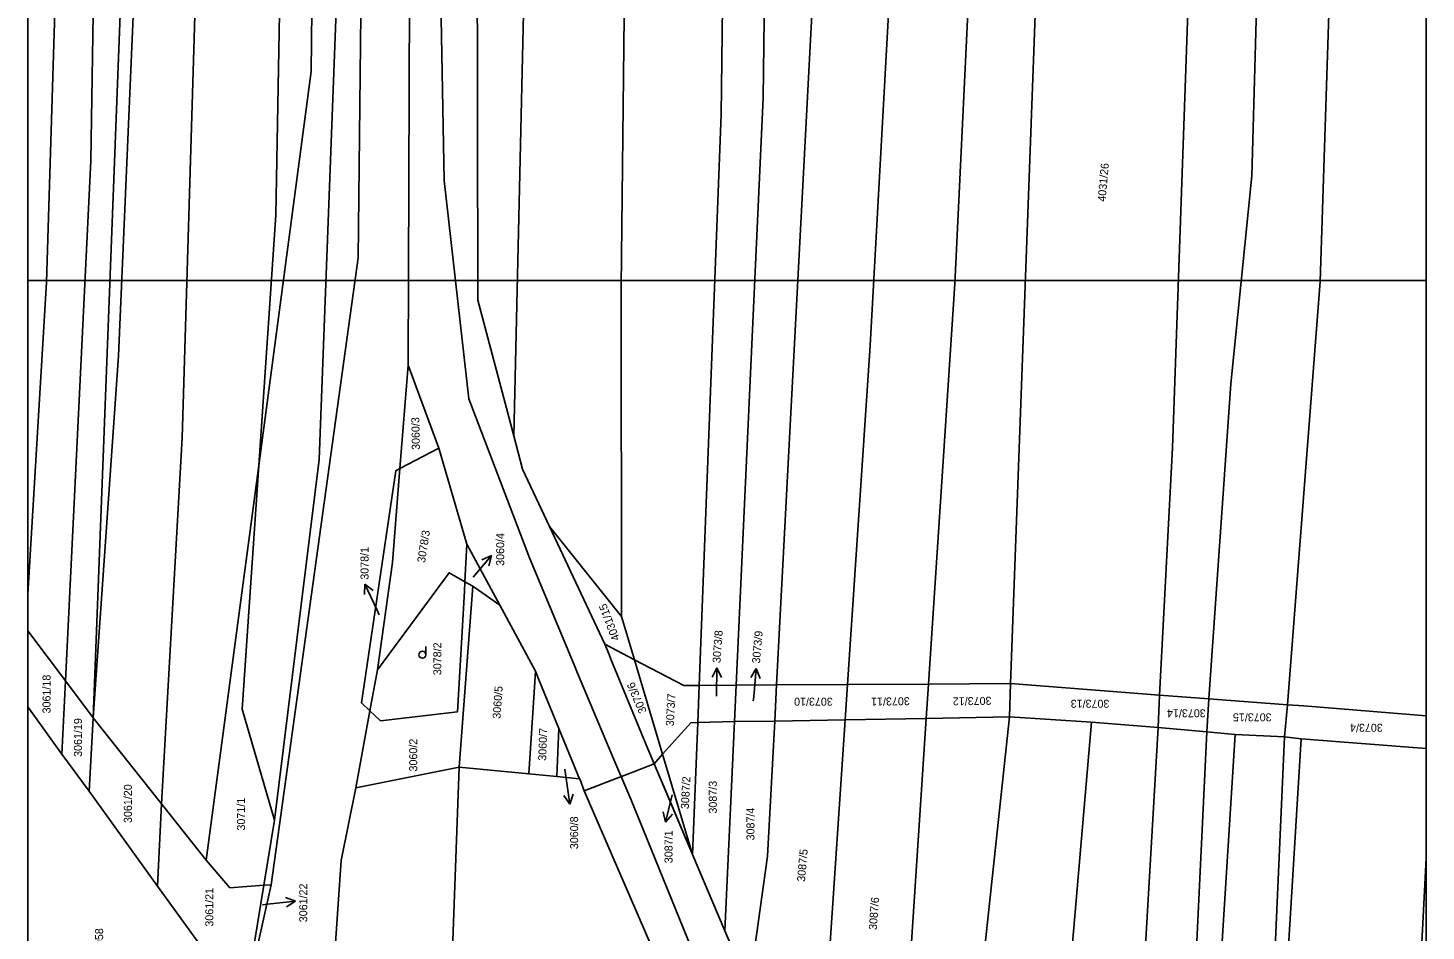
# Model space of a CAD drawing. Extents: x -534410 to -534262, y -1190162 to -1189584.
# Drawn here: x -534410.1 to -534261.6, y -1189968.6 to -1189872.7 of the extents above; entities that cross this region are included whole.
import ezdxf

# ---------------------------------------------------------------- set-up
doc = ezdxf.new("R2010")
doc.units = 0
for name, color, linetype in [('_KN_Povodí_Moravy', 7, 'Continuous'), ('_N_osa', 7, 'Continuous'), ('_rámeček', 7, 'Continuous'), ('_rámeček_mřížka', 7, 'Continuous'), ('Hranice parcel', 7, 'Continuous'), ('Parcelní čísla', 7, 'Continuous'), ('Pop  PČ popisy', 7, 'Continuous'), ('Značky kultur', 7, 'Continuous')]:
    doc.layers.add(name, color=color, linetype=linetype)

msp = doc.modelspace()

# ---------------------------------------------------------------- linework, layer by layer
at = {"layer": '_KN_Povodí_Moravy'}
for p, q in [((-534369.38, -1189820.8), (-534369.75, -1189908.47)), ((-534358.53, -1189915.98), (-534362.34, -1189901.56)), ((-534369.75, -1189908.47), (-534366.49, -1189917.27)), ((-534366.49, -1189917.27), (-534363.5, -1189927.49)), ((-534348.85, -1189938.1), (-534354.73, -1189925.6)), ((-534360.01, -1189933.96), (-534356.23, -1189940.98)), ((-534356.23, -1189940.98), (-534355.84, -1189941.94)), ((-534355.84, -1189941.94), (-534353.75, -1189947.04)), ((-534353.75, -1189947.04), (-534351.79, -1189951.81)), ((-534346.53, -1189951.94), (-534343.61, -1189950.82)), ((-534351.52, -1189952.39), (-534351.04, -1189953.66)), ((-534351.04, -1189953.66), (-534347.64, -1189952.36)), ((-534347.64, -1189952.36), (-534346.53, -1189951.94)), ((-534351.04, -1189953.66), (-534341.9, -1189974.75)), ((-534336.09, -1189968.55), (-534339.54, -1189960.43)), ((-534333.52, -1189974.6), (-534336.09, -1189968.55))]:
    msp.add_line(p, q, dxfattribs=at)
for points in [[(-534362.34, -1189901.56), (-534362.6, -1189764.35), (-534359.48, -1189697.97)], [(-534354.73, -1189925.6), (-534357.59, -1189919.52), (-534358.53, -1189915.98)], [(-534363.5, -1189927.49), (-534362.09, -1189930.1), (-534360.01, -1189933.96)], [(-534343.61, -1189950.82), (-534344.09, -1189949.7), (-534344.29, -1189949.21), (-534348.2, -1189939.68), (-534348.39, -1189939.21), (-534348.85, -1189938.1)], [(-534343.61, -1189950.82), (-534346.53, -1189951.94), (-534347.64, -1189952.36), (-534351.04, -1189953.66)], [(-534339.54, -1189960.43), (-534341.89, -1189954.88), (-534343.61, -1189950.82)], [(-534351.79, -1189951.81), (-534351.6, -1189952.27), (-534351.52, -1189952.39)]]:
    msp.add_lwpolyline(points, dxfattribs=at)
at = {"layer": '_N_osa'}
for points in [[(-534351.95, -1189940.72), (-534356.84, -1189928.92), (-534363.29, -1189912.04), (-534365.92, -1189888.84), (-534366.71, -1189846.73), (-534366.46, -1189820.49), (-534366.39, -1189779.5), (-534366.3, -1189748.87), (-534365.06, -1189684.89), (-534363.19, -1189653.56), (-534361.33, -1189627.82)], [(-534347.89, -1189950.33), (-534351.93, -1189940.77), (-534351.95, -1189940.72)], [(-534327.36, -1190134.6), (-534324.33, -1190120.41), (-534323.46, -1190078.16), (-534322.63, -1190051.74), (-534322.66, -1190021.45), (-534325.42, -1190005.39), (-534346.1, -1189954.57), (-534347.89, -1189950.33)]]:
    msp.add_lwpolyline(points, dxfattribs=at)
at = {"layer": '_rámeček'}
msp.add_line((-534410.13, -1189584.47), (-534410.13, -1190161.97), dxfattribs=at)
msp.add_lwpolyline([(-534410.13, -1190161.97), (-534261.63, -1190161.97), (-534261.63, -1189584.47)], dxfattribs=at)
for points in [[(-534410.13, -1189794.47), (-534261.63, -1189794.47), (-534261.63, -1189899.47), (-534410.13, -1189899.47)], [(-534410.13, -1189899.47), (-534261.63, -1189899.47), (-534261.63, -1190004.47), (-534410.13, -1190004.47)]]:
    msp.add_lwpolyline(points, close=True, dxfattribs=at)
at = {"layer": '_rámeček_mřížka'}
for p, q in [((-534410.13, -1189584.47), (-534410.13, -1190161.97)), ((-534407.13, -1189899.47), (-534410.13, -1189899.47)), ((-534264.63, -1189899.47), (-534261.63, -1189899.47))]:
    msp.add_line(p, q, dxfattribs=at)
msp.add_lwpolyline([(-534410.13, -1190161.97), (-534261.63, -1190161.97), (-534261.63, -1189584.47)], dxfattribs=at)
at = {"layer": 'Hranice parcel'}
for p, q in [((-534403.19, -1189945.91), (-534398.3, -1189817.87)), ((-534369.75, -1189908.47), (-534369.38, -1189820.8)), ((-534305.77, -1189942.29), (-534301.62, -1189830.03)), ((-534362.34, -1189901.56), (-534358.53, -1189915.98)), ((-534370.62, -1189919.44), (-534369.75, -1189908.47)), ((-534366.49, -1189917.27), (-534369.75, -1189908.47)), ((-534370.62, -1189919.44), (-534366.49, -1189917.27)), ((-534363.5, -1189927.49), (-534366.49, -1189917.27)), ((-534391.18, -1189961.04), (-534385.61, -1189919.11)), ((-534354.73, -1189925.6), (-534348.85, -1189938.1)), ((-534354.73, -1189925.6), (-534347.07, -1189935.15)), ((-534363.5, -1189927.49), (-534363.72, -1189931.47)), ((-534360.01, -1189933.96), (-534363.5, -1189927.49)), ((-534363.72, -1189931.47), (-534363.77, -1189932.48)), ((-534362.87, -1189931.95), (-534363.72, -1189931.47)), ((-534362.87, -1189931.95), (-534360.01, -1189933.96)), ((-534356.23, -1189940.98), (-534360.01, -1189933.96)), ((-534345.7, -1189939.75), (-534347.07, -1189935.15)), ((-534406.13, -1189942), (-534410.13, -1189936.68)), ((-534345.7, -1189939.75), (-534348.85, -1189938.1)), ((-534373.8, -1189945.18), (-534373, -1189940.81)), ((-534342.72, -1189949.77), (-534345.7, -1189939.75)), ((-534340.46, -1189942.49), (-534345.7, -1189939.75)), ((-534406.54, -1189949.77), (-534406.13, -1189942)), ((-534403.19, -1189945.91), (-534406.13, -1189942)), ((-534355.84, -1189941.94), (-534356.23, -1189940.98)), ((-534353.75, -1189947.04), (-534355.84, -1189941.94)), ((-534314.47, -1189942.34), (-534323.08, -1189942.39)), ((-534314.72, -1189945.99), (-534314.47, -1189942.34)), ((-534305.77, -1189942.29), (-534314.47, -1189942.34)), ((-534305.87, -1189945.8), (-534305.77, -1189942.29)), ((-534289.92, -1189943.5), (-534305.77, -1189942.29)), ((-534338.84, -1189942.48), (-534340.46, -1189942.49)), ((-534338.98, -1189946.42), (-534338.84, -1189942.48)), ((-534334.89, -1189942.46), (-534338.84, -1189942.48)), ((-534335.08, -1189946.31), (-534334.89, -1189942.46)), ((-534330.63, -1189942.43), (-534334.89, -1189942.46)), ((-534330.81, -1189946.26), (-534330.63, -1189942.43)), ((-534323.08, -1189942.39), (-534330.63, -1189942.43)), ((-534323.33, -1189946.13), (-534323.08, -1189942.39)), ((-534290.08, -1189946.94), (-534289.92, -1189943.5)), ((-534284.68, -1189943.89), (-534289.92, -1189943.5)), ((-534410.13, -1189944.76), (-534406.54, -1189949.77)), ((-534375.31, -1189953.34), (-534373.8, -1189945.18)), ((-534284.92, -1189947.42), (-534284.68, -1189943.89)), ((-534276.35, -1189944.53), (-534284.68, -1189943.89)), ((-534276.35, -1189944.53), (-534276.65, -1189947.93)), ((-534403.61, -1189953.7), (-534403.19, -1189945.91)), ((-534395.93, -1189955.06), (-534403.19, -1189945.91)), ((-534339.54, -1189960.43), (-534338.98, -1189946.42)), ((-534338.98, -1189946.42), (-534335.08, -1189946.31)), ((-534336.09, -1189968.55), (-534335.08, -1189946.31)), ((-534335.08, -1189946.31), (-534330.81, -1189946.26)), ((-534330.81, -1189946.26), (-534323.33, -1189946.13)), ((-534326.36, -1189991.44), (-534323.33, -1189946.13)), ((-534323.33, -1189946.13), (-534314.72, -1189945.99)), ((-534319.25, -1190015.38), (-534314.72, -1189945.99)), ((-534314.72, -1189945.99), (-534305.87, -1189945.8)), ((-534313.21, -1190014.59), (-534305.87, -1189945.8)), ((-534305.87, -1189945.8), (-534297.16, -1189946.38)), ((-534302.34, -1190006.82), (-534297.16, -1189946.38)), ((-534297.16, -1189946.38), (-534290.08, -1189946.94)), ((-534353.94, -1189952.16), (-534353.75, -1189947.04)), ((-534351.79, -1189951.81), (-534353.75, -1189947.04)), ((-534290.08, -1189946.94), (-534297.41, -1190071.61)), ((-534291.17, -1190079.8), (-534284.92, -1189947.42)), ((-534290.2, -1190079.83), (-534281.9, -1189947.69)), ((-534290.08, -1189946.94), (-534284.92, -1189947.42)), ((-534284.92, -1189947.42), (-534281.9, -1189947.69)), ((-534281.9, -1189947.69), (-534276.65, -1189947.93)), ((-534281.42, -1190056.27), (-534276.65, -1189947.93)), ((-534281.42, -1190056.27), (-534274.89, -1189948.14)), ((-534276.65, -1189947.93), (-534274.89, -1189948.14)), ((-534274.89, -1189948.14), (-534261.63, -1189949.19)), ((-534406.54, -1189949.77), (-534403.61, -1189953.7)), ((-534343.61, -1189950.82), (-534342.72, -1189949.77)), ((-534339.54, -1189960.43), (-534342.72, -1189949.77)), ((-534375.31, -1189953.34), (-534364.31, -1189951.16)), ((-534364.31, -1189951.16), (-534356.92, -1189951.87)), ((-534339.54, -1189960.43), (-534343.61, -1189950.82)), ((-534356.92, -1189951.87), (-534353.94, -1189952.16)), ((-534353.94, -1189952.16), (-534351.89, -1189952.35)), ((-534351.89, -1189952.35), (-534351.52, -1189952.39)), ((-534351.04, -1189953.66), (-534351.52, -1189952.39)), ((-534403.61, -1189953.7), (-534396.36, -1189963.8)), ((-534351.04, -1189953.66), (-534341.9, -1189974.75)), ((-534396.36, -1189963.8), (-534395.93, -1189955.06)), ((-534391.18, -1189961.04), (-534395.93, -1189955.06)), ((-534385.09, -1189963.71), (-534383.94, -1189956.8)), ((-534336.09, -1189968.55), (-534339.54, -1189960.43)), ((-534261.63, -1189960.81), (-534266.24, -1190056.9)), ((-534396.36, -1189963.8), (-534387.17, -1189976.47)), ((-534384.28, -1189963.65), (-534387.17, -1189976.47)), ((-534387.17, -1189976.47), (-534385.09, -1189963.71)), ((-534384.28, -1189963.65), (-534385.09, -1189963.71)), ((-534333.52, -1189974.6), (-534336.09, -1189968.55))]:
    msp.add_line(p, q, dxfattribs=at)
for points in [[(-534347.07, -1189935.15), (-534347.12, -1189900.1), (-534346.3, -1189826.77), (-534344.77, -1189736.43), (-534342.85, -1189658.07), (-534338.33, -1189584.47)], [(-534338.84, -1189942.48), (-534336.49, -1189881.83), (-534334.78, -1189743.85), (-534331.69, -1189634.65)], [(-534334.89, -1189942.46), (-534332.03, -1189880.06), (-534330.32, -1189744.92), (-534328.5, -1189646.74), (-534327.9, -1189634.55)], [(-534330.63, -1189942.43), (-534326.4, -1189862.47), (-534326.07, -1189744.82), (-534325.13, -1189646.79), (-534324.46, -1189634.65)], [(-534323.08, -1189942.39), (-534320.68, -1189906.36), (-534317.14, -1189842.3), (-534318.66, -1189746.11), (-534316.5, -1189653.71)], [(-534314.47, -1189942.34), (-534311.69, -1189899.83), (-534309.24, -1189848.85), (-534310.92, -1189745.14), (-534308.43, -1189653.71)], [(-534284.68, -1189943.89), (-534282.37, -1189910.46), (-534280.12, -1189888.37), (-534278.75, -1189838.65), (-534276.86, -1189771.85), (-534276.43, -1189752.24), (-534275.19, -1189689.29)], [(-534359.48, -1189697.97), (-534362.6, -1189764.35), (-534362.34, -1189901.56)], [(-534359.48, -1189697.97), (-534360.42, -1189747.8), (-534359.17, -1189788.69), (-534356.86, -1189843.2), (-534358.53, -1189915.98)], [(-534395.93, -1189955.06), (-534393.76, -1189916.2), (-534389.49, -1189774.63), (-534390.92, -1189749.37)], [(-534385.61, -1189919.11), (-534380.06, -1189877.29), (-534378.67, -1189750.28)], [(-534385.61, -1189919.11), (-534383.81, -1189892.54), (-534382.22, -1189804.86), (-534381.85, -1189775.86), (-534383.09, -1189750.44)], [(-534383.94, -1189956.8), (-534379.19, -1189918.48), (-534376.74, -1189853.94), (-534375.92, -1189797.44), (-534376.41, -1189774.02), (-534378.12, -1189750.26)], [(-534406.13, -1189942), (-534403.45, -1189886.77), (-534402.68, -1189837.82), (-534401.95, -1189776.76), (-534406.3, -1189754), (-534406.48, -1189752.31)], [(-534373.61, -1189764.09), (-534375.04, -1189897.07), (-534384.28, -1189963.65)], [(-534410.13, -1189932.79), (-534408.16, -1189899.66), (-534406.57, -1189847.9), (-534405.68, -1189781.38), (-534406.95, -1189766.9)], [(-534276.35, -1189944.53), (-534272.88, -1189899.59), (-534271.33, -1189851.42), (-534268.75, -1189786.35)], [(-534403.19, -1189945.91), (-534400.52, -1189907.49), (-534398.39, -1189858.23), (-534398.3, -1189817.87)], [(-534289.92, -1189943.5), (-534288.56, -1189917.25), (-534286.37, -1189854.83), (-534285.48, -1189830.14)], [(-534358.53, -1189915.98), (-534357.59, -1189919.52), (-534354.73, -1189925.6)], [(-534383.94, -1189956.8), (-534387.37, -1189945.01), (-534385.61, -1189919.11)], [(-534373.8, -1189945.18), (-534374.7, -1189944.34), (-534371.06, -1189919.67), (-534370.62, -1189919.44)], [(-534373, -1189940.81), (-534371.42, -1189929.41), (-534370.69, -1189920.31), (-534370.62, -1189919.44)], [(-534363.72, -1189931.47), (-534364.64, -1189930.95), (-534365.4, -1189930.52), (-534373, -1189940.81)], [(-534364.31, -1189951.16), (-534363.86, -1189945.04), (-534362.87, -1189931.95)], [(-534363.77, -1189932.48), (-534364.49, -1189945.28), (-534372.67, -1189946.23), (-534373.8, -1189945.18)], [(-534348.85, -1189938.1), (-534348.39, -1189939.21), (-534348.2, -1189939.68), (-534344.29, -1189949.21), (-534344.09, -1189949.7), (-534343.61, -1189950.82)], [(-534356.92, -1189951.87), (-534356.3, -1189942.12), (-534356.23, -1189940.98)], [(-534261.63, -1189945.72), (-534274.61, -1189944.66), (-534276.35, -1189944.53)], [(-534342.72, -1189949.77), (-534339.72, -1189946.46), (-534338.98, -1189946.42)], [(-534333.52, -1189974.6), (-534331.59, -1189960.61), (-534330.81, -1189946.26)], [(-534365.84, -1190003.05), (-534365.09, -1189972.48), (-534364.31, -1189951.16)], [(-534343.61, -1189950.82), (-534346.53, -1189951.94), (-534347.64, -1189952.36), (-534351.04, -1189953.66)], [(-534351.52, -1189952.39), (-534351.6, -1189952.27), (-534351.79, -1189951.81)], [(-534377.74, -1189975.71), (-534377.67, -1189972.94), (-534376.87, -1189961.07), (-534375.31, -1189953.34)], [(-534385.09, -1189963.71), (-534388.68, -1189963.97), (-534391.18, -1189961.04)]]:
    msp.add_lwpolyline(points, dxfattribs=at)
at = {"layer": 'Pop  PČ popisy'}
for p, q in [((-534362.83, -1189930.98), (-534360.9, -1189928.68)), ((-534360.9, -1189928.68), (-534361.93, -1189929.13)), ((-534360.9, -1189928.68), (-534361.16, -1189929.77)), ((-534374.34, -1189931.71), (-534374.37, -1189932.83)), ((-534373.07, -1189934.43), (-534374.34, -1189931.71)), ((-534374.34, -1189931.71), (-534373.46, -1189932.41)), ((-534372.81, -1189934.98), (-534373.07, -1189934.43)), ((-534336.94, -1189940.61), (-534337.46, -1189941.6)), ((-534336.99, -1189943.61), (-534336.94, -1189940.61)), ((-534336.94, -1189940.61), (-534336.46, -1189941.62)), ((-534332.77, -1189940.69), (-534333.36, -1189941.64)), ((-534333.04, -1189943.68), (-534332.77, -1189940.69)), ((-534332.77, -1189940.69), (-534332.36, -1189941.73)), ((-534333.08, -1189944.11), (-534333.04, -1189943.68)), ((-534353.1, -1189951.37), (-534352.99, -1189952.12)), ((-534352.99, -1189952.12), (-534352.57, -1189955.09)), ((-534352.57, -1189955.09), (-534353.21, -1189954.17)), ((-534352.57, -1189955.09), (-534352.22, -1189954.03)), ((-534341.7, -1189954.09), (-534342.4, -1189957)), ((-534342.4, -1189957), (-534342.66, -1189955.91)), ((-534342.4, -1189957), (-534341.68, -1189956.15)), ((-534385.2, -1189965.77), (-534384.7, -1189965.72)), ((-534384.7, -1189965.72), (-534381.71, -1189965.41)), ((-534381.71, -1189965.41), (-534382.76, -1189965.01)), ((-534381.71, -1189965.41), (-534382.66, -1189966.01))]:
    msp.add_line(p, q, dxfattribs=at)
at = {"layer": 'Značky kultur'}
msp.add_line((-534367.86, -1189939.22), (-534367.86, -1189938.35), dxfattribs=at)
msp.add_circle((-534368.23, -1189939.22), 0.375, dxfattribs=at)

# ---------------------------------------------------------------- texts
at = {"layer": 'Parcelní čísla'}
for s, rotation, p in [('4031/26', 85, (-534295.67, -1189891.13)), ('3060/3', 91, (-534368.5, -1189917.46)), ('3078/3', 81, (-534367.96, -1189929.5)), ('3060/4', 90, (-534359.54, -1189929.78)), ('3078/1', 90, (-534373.95, -1189931.25)), ('4031/15', 111, (-534347.25, -1189937.55)), ('3073/8', 86, (-534336.57, -1189940.12)), ('3073/9', 85, (-534332.38, -1189940.18)), ('3078/2', 90, (-534366.22, -1189941.39)), ('3061/18', 90, (-534407.73, -1189945.45)), ('3073/6', 113.2477, (-534344.39, -1189945.24)), ('3060/5', 86, (-534359.94, -1189946.04)), ('3073/7', 87, (-534341.53, -1189946.83)), ('3073/10', 180, (-534324.64, -1189943.78)), ('3073/11', 181, (-534316.47, -1189943.72)), ('3073/12', 181, (-534307.79, -1189943.68)), ('3073/13', 180, (-534295.26, -1189944)), ('3073/14', 180, (-534285.03, -1189945.01)), ('3061/19', 90, (-534404.39, -1189950.07)), ('3073/15', 180, (-534278.03, -1189945.44)), ('3073/4', 180, (-534266.22, -1189946.55)), ('3060/2', 90, (-534368.78, -1189951.62)), ('3060/7', 88, (-534355.09, -1189950.49)), ('3087/2', 87, (-534339.94, -1189955.63)), ('3087/3', 90, (-534336.96, -1189956.09)), ('3061/20', 90, (-534399.09, -1189957.09)), ('3071/1', 90, (-534387.07, -1189957.89)), ('3087/4', 90, (-534332.96, -1189958.94)), ('3060/8', 90, (-534351.69, -1189959.87)), ('3087/1', 90, (-534341.66, -1189961.36)), ('3087/5', 85, (-534327.6, -1189963.36)), ('3061/21', 90, (-534390.44, -1189968.1)), ('3061/22', 90, (-534380.46, -1189967.63)), ('3087/6', 86, (-534319.97, -1189968.47)), ('3058', 90, (-534402.14, -1189970.8))]:
    msp.add_text(s, height=0.85, rotation=rotation, dxfattribs=at).set_placement(p)

doc.saveas('drawing.dxf')
